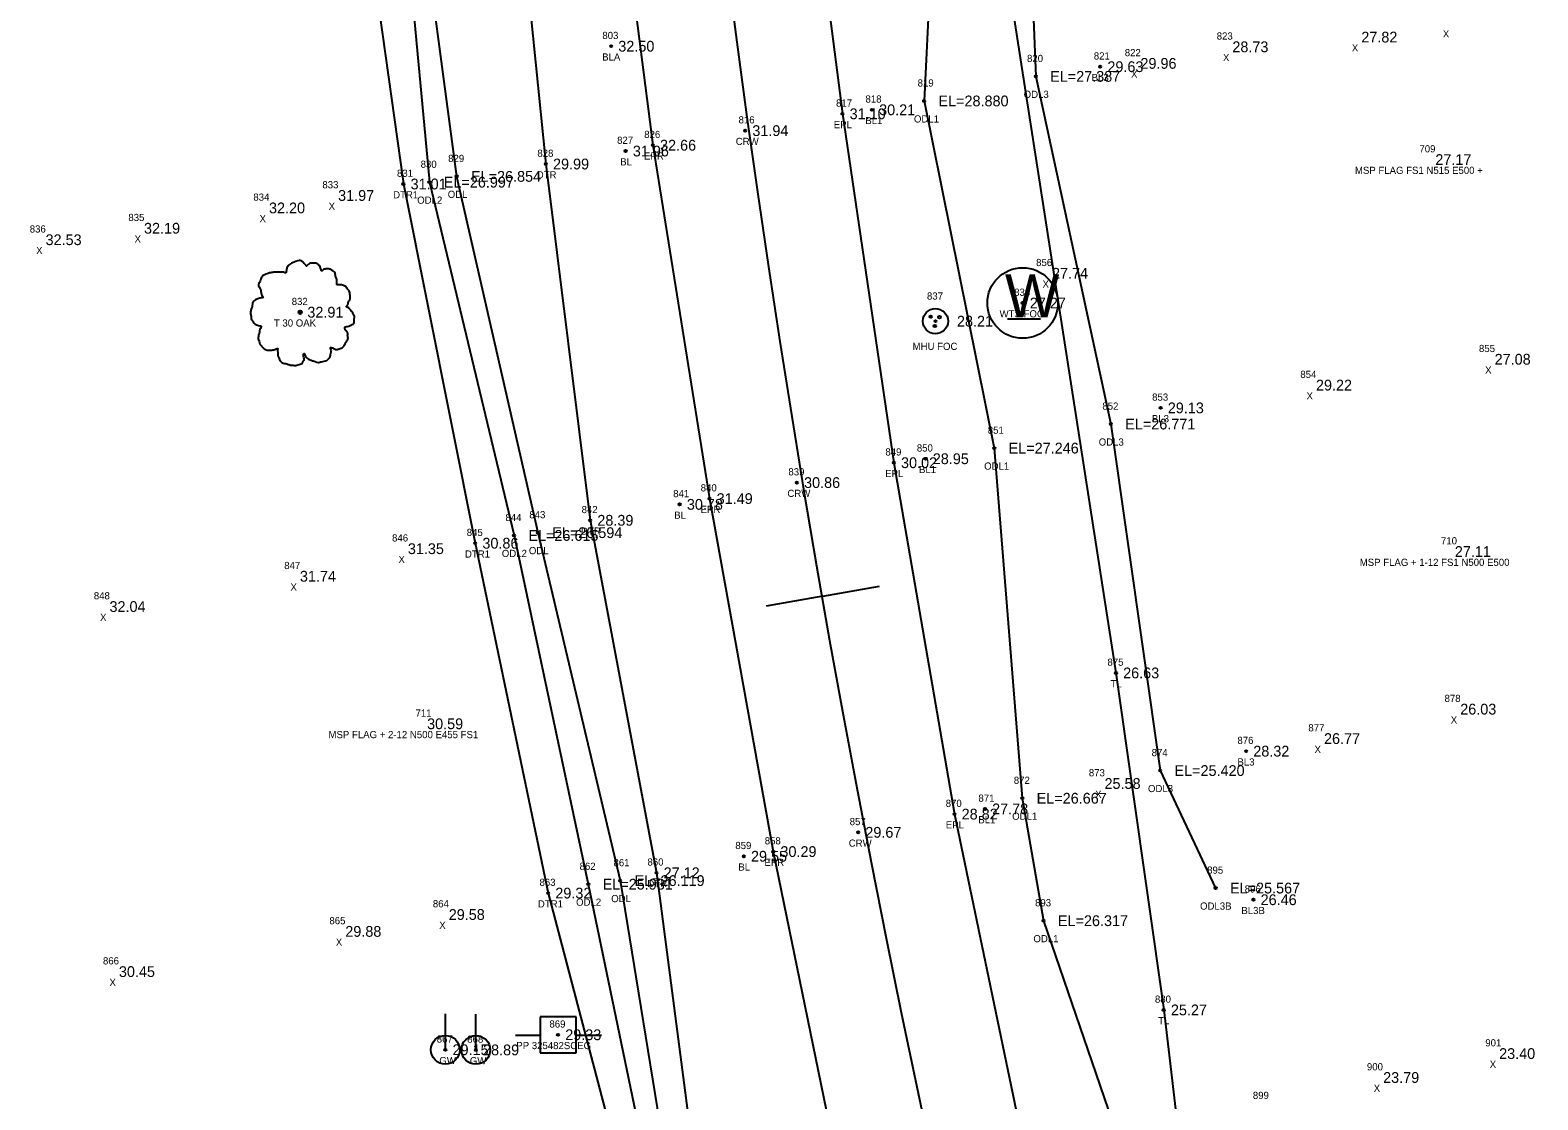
# Model space of a CAD drawing. Extents: x 2042117 to 2045853, y 303080 to 309569.
# Drawn here: x 2042758.3 to 2042968.2, y 306948.4 to 307097.3 of the extents above; entities that cross this region are included whole.
import ezdxf

# ---------------------------------------------------------------- set-up
doc = ezdxf.new("R2010")
doc.units = 0
for name, color, linetype in [('RD_DTM_BkLn_txCode', 7, 'Continuous'), ('RD_EX_DR_Inlet', 7, 'Continuous'), ('RD_EX_H2O', 7, 'Continuous'), ('RD_EX_H2O_txCode', 7, 'Continuous'), ('RD_EX_Misc_txCode', 7, 'Continuous'), ('RD_EX_Road', 7, 'Continuous'), ('RD_EX_Road_txCode', 7, 'Continuous'), ('RD_EX_TX_H2O_ELEV', 7, 'Continuous'), ('RD_EX_TX_Misc_ELEV', 7, 'Continuous'), ('RD_EX_TX_Road_ELEV', 7, 'Continuous'), ('RD_EX_TX_UT_ELEV', 7, 'Continuous'), ('RD_EX_TX_VEG_ELEV', 7, 'Continuous'), ('RD_EX_UT', 7, 'Continuous'), ('RD_EX_UT_txCode', 7, 'Continuous'), ('RD_EX_VEG', 7, 'Continuous'), ('RD_EX_VEG_txCode', 7, 'Continuous'), ('RD_HC_Cl', 7, 'Continuous'), ('RD_HC_Data_Tic', 7, 'Continuous'), ('RD_HC_Survey_ELEV', 7, 'Continuous'), ('RD_HC_Survey_txCode', 7, 'Continuous'), ('RD_SMD_Locator', 7, 'Continuous')]:
    doc.layers.add(name, color=color, linetype=linetype)

msp = doc.modelspace()

# ---------------------------------------------------------------- linework, layer by layer
at = {"layer": 'RD_EX_DR_Inlet'}
for centre, radius in [((2042884.32, 307056.83), 1.75), ((2042883.66, 307057.46), 0.175), ((2042884.88, 307057.39), 0.175), ((2042884.24, 307056.17), 0.175)]:
    msp.add_circle(centre, radius, dxfattribs=at)
at = {"layer": 'RD_EX_H2O'}
for points in [[(2042865.43, 307427.05), (2042866.84, 307378.87), (2042866.82, 307329.93), (2042876.23, 307282.16), (2042878.43, 307232.86), (2042875.08, 307184.77), (2042887.19, 307136.65), (2042884.32, 307120.02), (2042882.74, 307087.49), (2042892.51, 307039.16), (2042896.41, 306990.42), (2042899.37, 306973.37), (2042910.05, 306942.23), (2042920.75, 306896.67), (2042927.15, 306846.78), (2042945.6, 306801.59), (2042960.32, 306754.61), (2042976.65, 306708.74), (2042994.63, 306662.76), (2043013.3, 306616.98), (2043029.17, 306571.91), (2043050.77, 306528.53)], [(2042809.74, 307126.16), (2042806.56, 307122.63), (2042790.31, 307116.78), (2042788.49, 307114.78), (2042791.89, 307113.57), (2042804.81, 307114.94), (2042810.25, 307075.93), (2042820.25, 307025.92), (2042830.4, 306977.21), (2042843.29, 306928.12), (2042852.91, 306878.24), (2042864.55, 306828.43), (2042879.23, 306781.72), (2042889.45, 306748.73), (2042886.16, 306741.98), (2042888.34, 306727.94), (2042896.13, 306676.35), (2042885.67, 306665.43), (2042857.25, 306612.72)], [(2042809.74, 307126.16), (2042815.01, 307124.31), (2042821.79, 307118.99), (2042825.8, 307110.2), (2042827.88, 307100.21), (2042830.08, 307078.71), (2042836.25, 307029.11), (2042845.48, 306980.04), (2042852.07, 306929.46), (2042864.58, 306881.26), (2042879.31, 306833.06), (2042893.37, 306784.78), (2042908.76, 306736.23), (2042928.77, 306689.39), (2042938.94, 306669.11)], [(2042896.98, 307122.86), (2042898.29, 307090.91), (2042908.74, 307042.51), (2042915.6, 306994.27), (2042923.33, 306977.91)], [(2042810.02, 307117.36), (2042813.87, 307076.18), (2042825.65, 307027), (2042835.99, 306978.45), (2042846.19, 306929.27), (2042857.5, 306879.97), (2042870.3, 306830.67), (2042885.37, 306782.68), (2042895.57, 306748.28), (2042892.03, 306740.63), (2042891.66, 306731.27), (2042905.95, 306680.58), (2042906.87, 306643.18), (2042864.97, 306605.63)], [(2042812.2, 307117.75), (2042817.66, 307076.99), (2042828.97, 307027.39), (2042840.42, 306978.95), (2042848.44, 306929.66), (2042859.84, 306880.36), (2042873.68, 306831.67), (2042888.54, 306783.43), (2042900.59, 306749.27), (2042902.9, 306733.67), (2042926.04, 306688.21), (2042936.45, 306668.37), (2042947.44, 306643.99), (2042966.18, 306597.91), (2042985.34, 306551.14), (2042987.61, 306538.59)]]:
    msp.add_lwpolyline(points, dxfattribs=at)
at = {"layer": 'RD_EX_Road'}
for points in [[(2042828.36, 307428.87), (2042826.99, 307378.91), (2042826.88, 307329.29), (2042828.01, 307279.82), (2042830.5, 307230.24), (2042834.09, 307180.37), (2042835.89, 307157.73), (2042833.55, 307154.38), (2042836.54, 307132.83), (2042837.33, 307130.11), (2042837.64, 307128.77), (2042839.22, 307126.16), (2042844.98, 307081.33), (2042852.86, 307032.13), (2042861.74, 306982.99), (2042871.66, 306934.62), (2042883.38, 306885.88), (2042895.94, 306837.56), (2042909.76, 306789.89)], [(2042855.03, 307427.78), (2042853.64, 307379.19), (2042853.31, 307329.44), (2042854.43, 307281.38), (2042857.15, 307232.07), (2042860.27, 307183.35), (2042865.16, 307133.89), (2042871.37, 307085.7), (2042878.53, 307037.13), (2042886.97, 306988.21), (2042897.02, 306940.01), (2042908.28, 306892.66), (2042921.09, 306844.85), (2042934.41, 306798.2)]]:
    msp.add_lwpolyline(points, dxfattribs=at)
at = {"layer": 'RD_EX_UT'}
for p, q in [((2042894.34, 307057.15), (2042898.96, 307057.15)), ((2042816.09, 306955.4), (2042816.09, 306960.4)), ((2042820.34, 306955.38), (2042820.34, 306960.38)), ((2042834.28, 306959.99), (2042829.28, 306959.99)), ((2042829.28, 306959.99), (2042829.28, 306954.99)), ((2042834.28, 306954.99), (2042834.28, 306959.99)), ((2042825.84, 306957.43), (2042829.31, 306957.43)), ((2042834.2, 306957.43), (2042837.84, 306957.43)), ((2042829.28, 306954.99), (2042834.28, 306954.99))]:
    msp.add_line(p, q, dxfattribs=at)
for centre, radius in [((2042896.46, 307059.36), 4.91), ((2042816.09, 306955.4), 2), ((2042820.34, 306955.38), 2)]:
    msp.add_circle(centre, radius, dxfattribs=at)
at = {"layer": 'RD_EX_VEG'}
msp.add_lwpolyline([(2042885.61, 307482.85), (2042881.1, 307379.92), (2042880.44, 307351.7), (2042880.19, 307284.9), (2042884.99, 307224.08), (2042886.48, 307195.22), (2042890.83, 307127.55), (2042909.45, 307007.86), (2042916.1, 306960.95), (2042918.56, 306940.03), (2042926.66, 306909), (2042942.91, 306849.91), (2042954.33, 306802.72), (2042963.56, 306806.84), (2042974.33, 306847.25), (2043002.07, 306860.54), (2043032.14, 306846.51)], dxfattribs=at)
for centre, radius in [((2042795.88, 307058.08), 0.25), ((2042795.87, 307058.06), 0.0001)]:
    msp.add_circle(centre, radius, dxfattribs=at)
for points in [[(2042796.02, 307065.25), (2042795.72, 307065.27), (2042795.39, 307065.17), (2042795.14, 307065.07), (2042794.92, 307065), (2042794.69, 307064.9), (2042794.39, 307064.72), (2042794.17, 307064.52), (2042794.04, 307064.27), (2042793.99, 307064.05), (2042793.94, 307063.77), (2042793.94, 307063.6), (2042793.82, 307063.57), (2042793.67, 307063.6), (2042793.42, 307063.67), (2042793.17, 307063.67), (2042792.92, 307063.67), (2042792.57, 307063.65), (2042792.22, 307063.65), (2042791.94, 307063.6), (2042791.62, 307063.55), (2042791.24, 307063.42), (2042790.89, 307063.3), (2042790.59, 307063.05), (2042790.34, 307062.57), (2042790.22, 307062.22), (2042790.07, 307061.97), (2042790.22, 307061.52), (2042790.39, 307061.17), (2042790.42, 307060.97), (2042790.49, 307060.55), (2042790.59, 307060.33), (2042790.72, 307060.13), (2042790.64, 307060.1), (2042790.27, 307060.05), (2042789.97, 307059.95), (2042789.54, 307059.73), (2042789.32, 307059.5), (2042789.22, 307059.18), (2042789.19, 307058.83), (2042789.09, 307058.63), (2042789.02, 307058.35), (2042788.99, 307058.28), (2042788.94, 307057.95), (2042789.04, 307057.5), (2042789.07, 307057.15), (2042789.19, 307056.93), (2042789.34, 307056.75), (2042789.52, 307056.5), (2042789.92, 307056.28), (2042790.24, 307056.18), (2042790.44, 307056.15), (2042790.27, 307055.65), (2042790.22, 307055.3), (2042790.09, 307054.9), (2042790.09, 307054.83), (2042790.04, 307054.35), (2042790.19, 307054.03), (2042790.27, 307053.65), (2042790.44, 307053.43), (2042790.72, 307053.13), (2042791.04, 307052.9), (2042791.54, 307052.78), (2042791.94, 307052.8), (2042792.52, 307052.98), (2042792.77, 307053.05), (2042792.74, 307052.88), (2042792.77, 307052.5), (2042792.77, 307052.08), (2042792.92, 307051.75), (2042793.02, 307051.48), (2042793.17, 307051.23), (2042793.49, 307051), (2042793.89, 307050.93), (2042794.32, 307050.78), (2042794.77, 307050.7), (2042795.27, 307050.68), (2042795.87, 307050.83), (2042796.14, 307050.95), (2042796.24, 307051.13), (2042796.44, 307051.5), (2042796.39, 307051.73), (2042796.42, 307052.33), (2042796.52, 307052.15), (2042796.69, 307051.8), (2042797.19, 307051.5), (2042797.59, 307051.33), (2042798.07, 307051.18), (2042798.36, 307051.1), (2042798.84, 307051.18), (2042799.21, 307051.25), (2042799.59, 307051.38), (2042799.89, 307051.65), (2042800.06, 307051.93), (2042800.11, 307052.2), (2042800.19, 307052.58), (2042800.24, 307052.75)], [(2042800.24, 307052.75), (2042800.16, 307052.93), (2042800.11, 307053.18), (2042800.19, 307053.15), (2042800.36, 307053.1), (2042800.64, 307052.98), (2042800.86, 307052.9), (2042801.19, 307052.93), (2042801.46, 307053.03), (2042801.91, 307053.3), (2042802.19, 307053.78), (2042802.46, 307054.18), (2042802.54, 307054.5), (2042802.49, 307054.73), (2042802.46, 307055.23), (2042802.26, 307055.48), (2042802.21, 307055.6), (2042802.11, 307056), (2042802.19, 307056.05), (2042802.46, 307056.1), (2042802.84, 307056.23), (2042803.11, 307056.35), (2042803.34, 307056.53), (2042803.41, 307056.75), (2042803.39, 307057.15), (2042803.44, 307057.55), (2042803.36, 307057.7), (2042803.26, 307057.85), (2042803.19, 307058.05), (2042803.04, 307058.2), (2042802.94, 307058.35), (2042802.84, 307058.45), (2042802.71, 307058.6), (2042802.54, 307058.73), (2042802.39, 307058.78), (2042802.34, 307058.93), (2042802.49, 307059.13), (2042802.54, 307059.23), (2042802.56, 307059.45), (2042802.79, 307059.8), (2042802.84, 307060.2), (2042802.79, 307060.62), (2042802.74, 307060.9), (2042802.59, 307061.17), (2042802.39, 307061.42), (2042802.26, 307061.6), (2042802.09, 307061.72), (2042801.76, 307061.85), (2042801.51, 307061.9), (2042801.16, 307061.9), (2042800.96, 307061.95), (2042800.99, 307062), (2042800.99, 307062.15), (2042800.99, 307062.42), (2042800.91, 307062.87), (2042800.76, 307063.37), (2042800.76, 307063.4), (2042800.66, 307063.65), (2042800.44, 307063.85), (2042800.26, 307063.95), (2042800.06, 307064.07), (2042799.81, 307064.1), (2042799.51, 307064.1), (2042799.24, 307064.05), (2042799.04, 307063.95), (2042798.86, 307063.82), (2042798.79, 307063.97), (2042798.69, 307064.27), (2042798.64, 307064.42), (2042798.49, 307064.6), (2042798.27, 307064.8), (2042797.82, 307064.92), (2042797.19, 307064.85), (2042796.89, 307064.65), (2042796.74, 307064.47), (2042796.69, 307064.6), (2042796.49, 307064.8), (2042796.39, 307064.97), (2042796.22, 307065.1), (2042796.07, 307065.2), (2042795.97, 307065.25)]]:
    msp.add_spline(points, degree=3, dxfattribs=at)
at = {"layer": 'RD_HC_Cl'}
msp.add_arc((2044751.25, 307348.43), 1911.29, 137.68184, 219.86836, dxfattribs=at)
at = {"layer": 'RD_HC_Data_Tic'}
for q in [(2042876.52, 307019.93), (2042860.76, 307017.17)]:
    msp.add_line((2042868.64, 307018.55), q, dxfattribs=at)
at = {"layer": 'RD_SMD_Locator'}
for centre in [(2042839.17, 307095.11), (2042907.26, 307092.26), (2042898.29, 307090.91), (2042875.48, 307086.26), (2042882.74, 307087.49), (2042871.37, 307085.7), (2042857.83, 307083.36), (2042841.19, 307080.52), (2042844.98, 307081.33), (2042830.08, 307078.71), (2042810.25, 307075.93), (2042813.87, 307076.18), (2042817.66, 307076.99), (2042896.46, 307059.36), (2042795.88, 307058.08), (2042884.32, 307056.83), (2042915.67, 307044.76), (2042908.74, 307042.51), (2042882.95, 307037.68), (2042892.51, 307039.16), (2042878.53, 307037.13), (2042865.03, 307034.36), (2042848.71, 307031.33), (2042852.86, 307032.13), (2042836.25, 307029.11), (2042825.65, 307027), (2042828.97, 307027.39), (2042820.25, 307025.92), (2042909.45, 307007.86), (2042927.57, 306996.97), (2042915.6, 306994.27), (2042896.41, 306990.42), (2042886.97, 306988.21), (2042891.21, 306988.93), (2042873.56, 306985.67), (2042861.74, 306982.99), (2042857.64, 306982.34), (2042840.42, 306978.95), (2042845.48, 306980.04), (2042830.4, 306977.21), (2042835.99, 306978.45), (2042923.33, 306977.91), (2042928.59, 306976.29), (2042899.37, 306973.37), (2042916.1, 306960.95), (2042831.78, 306957.49), (2042816.09, 306955.4), (2042820.34, 306955.38)]:
    msp.add_circle(centre, 0.15, dxfattribs=at)

# ---------------------------------------------------------------- texts
at = {"layer": 'RD_DTM_BkLn_txCode'}
for s, p in [('803', (2042837.95, 307096.11)), ('821', (2042906.37, 307093.26)), ('BLA', (2042837.92, 307093.11)), ('BL3', (2042906.06, 307090.26)), ('818', (2042874.58, 307087.26)), ('BL1', (2042874.56, 307084.26)), ('827', (2042840, 307081.52)), ('BL', (2042840.43, 307078.52)), ('853', (2042914.49, 307045.76)), ('BL3', (2042914.46, 307042.76)), ('850', (2042881.73, 307038.68)), ('BL1', (2042882.03, 307035.68)), ('841', (2042847.81, 307032.33)), ('BL', (2042847.95, 307029.33)), ('876', (2042926.36, 306997.97)), ('BL3', (2042926.36, 306994.97)), ('871', (2042890.31, 306989.93)), ('BL1', (2042890.29, 306986.93)), ('859', (2042856.46, 306983.34)), ('BL', (2042856.88, 306980.34)), ('896', (2042927.38, 306977.29)), ('BL3B', (2042926.91, 306974.29))]:
    msp.add_text(s, height=1, dxfattribs=at).set_placement(p)
at = {"layer": 'RD_EX_H2O_txCode'}
for s, p in [('820', (2042897.07, 307092.91)), ('819', (2042881.84, 307089.49)), ('ODL3', (2042896.6, 307087.91)), ('ODL1', (2042881.33, 307084.49)), ('829', (2042816.48, 307078.99)), ('828', (2042828.9, 307079.71)), ('831', (2042809.36, 307076.93)), ('830', (2042812.65, 307078.18)), ('DTR', (2042828.81, 307076.71)), ('DTR1', (2042808.82, 307073.93)), ('ODL2', (2042812.17, 307073.18)), ('ODL', (2042816.42, 307073.99)), ('852', (2042907.56, 307044.51)), ('851', (2042891.61, 307041.16)), ('ODL3', (2042907.05, 307039.51)), ('ODL1', (2042891.1, 307036.16)), ('844', (2042824.46, 307029)), ('843', (2042827.78, 307029.39)), ('842', (2042835.06, 307030.11)), ('845', (2042819.07, 307026.92)), ('DTR', (2042834.98, 307027.11)), ('ODL2', (2042823.95, 307024)), ('ODL', (2042827.72, 307024.39)), ('DTR1', (2042818.82, 307023.92)), ('874', (2042914.42, 306996.27)), ('872', (2042895.23, 306992.42)), ('ODL3', (2042913.91, 306991.27)), ('ODL1', (2042895, 306987.42)), ('862', (2042834.78, 306980.45)), ('861', (2042839.5, 306980.95)), ('860', (2042844.23, 306981.04)), ('895', (2042922.15, 306979.91)), ('863', (2042829.2, 306978.21)), ('DTR', (2042844.21, 306978.04)), ('ODL', (2042839.18, 306975.95)), ('DTR1', (2042828.97, 306975.21)), ('ODL2', (2042834.29, 306975.45)), ('893', (2042898.19, 306975.37)), ('ODL3B', (2042921.16, 306974.91)), ('ODL1', (2042897.96, 306970.37))]:
    msp.add_text(s, height=1, dxfattribs=at).set_placement(p)
at = {"layer": 'RD_EX_Misc_txCode'}
for s, p in [('823', (2042923.48, 307096.03)), ('X', (2042954.96, 307096.33)), ('822', (2042910.68, 307093.72)), ('X', (2042942.29, 307094.38)), ('X', (2042924.35, 307093.03)), ('X', (2042911.55, 307090.72)), ('709', (2042951.7, 307080.33)), ('MSP FLAG FS1 N515 E500 +', (2042942.72, 307077.33)), ('833', (2042798.97, 307075.33)), ('834', (2042789.36, 307073.6)), ('X', (2042799.84, 307072.33)), ('835', (2042771.96, 307070.77)), ('X', (2042790.22, 307070.6)), ('836', (2042758.23, 307069.17)), ('X', (2042759.12, 307066.17)), ('X', (2042772.82, 307067.77)), ('856', (2042898.34, 307064.5)), ('X', (2042899.23, 307061.5)), ('855', (2042959.99, 307052.53)), ('X', (2042960.85, 307049.53)), ('854', (2042935.12, 307048.93)), ('X', (2042935.98, 307045.93)), ('846', (2042808.67, 307026.16)), ('710', (2042954.7, 307025.76)), ('847', (2042793.66, 307022.32)), ('X', (2042809.56, 307023.16)), ('MSP FLAG + 1-12 FS1 N500 E500', (2042943.39, 307022.76)), ('848', (2042767.15, 307018.1)), ('X', (2042794.53, 307019.32)), ('X', (2042768.02, 307015.1)), ('878', (2042955.2, 307003.82)), ('711', (2042811.94, 307001.78)), ('877', (2042936.24, 306999.72)), ('X', (2042956.06, 307000.82)), ('MSP FLAG + 2-12 N500 E455 FS1', (2042799.82, 306998.78)), ('X', (2042937.1, 306996.72)), ('873', (2042905.68, 306993.47)), ('X', (2042906.55, 306990.47)), ('864', (2042814.35, 306975.23)), ('865', (2042799.95, 306972.88)), ('X', (2042815.24, 306972.23)), ('X', (2042800.84, 306969.88)), ('866', (2042768.42, 306967.28)), ('X', (2042769.33, 306964.28)), ('901', (2042960.87, 306955.87)), ('X', (2042961.49, 306952.87)), ('900', (2042944.39, 306952.54)), ('899', (2042928.51, 306948.55)), ('X', (2042945.34, 306949.54))]:
    msp.add_text(s, height=1, dxfattribs=at).set_placement(p)
at = {"layer": 'RD_EX_Road_txCode'}
for s, p in [('817', (2042870.48, 307086.7)), ('EPL', (2042870.17, 307083.7)), ('826', (2042843.78, 307082.33)), ('EPR', (2042843.75, 307079.33)), ('849', (2042877.35, 307038.13)), ('EPL', (2042877.32, 307035.13)), ('840', (2042851.64, 307033.13)), ('EPR', (2042851.63, 307030.13)), ('870', (2042885.75, 306989.21)), ('EPL', (2042885.76, 306986.21)), ('858', (2042860.56, 306983.99)), ('EPR', (2042860.51, 306980.99))]:
    msp.add_text(s, height=1, dxfattribs=at).set_placement(p)
at = {"layer": 'RD_EX_TX_H2O_ELEV'}
for s, p in [('EL=27.387', (2042900.29, 307090.16)), ('EL=28.880', (2042884.74, 307086.74)), ('EL=26.854', (2042819.66, 307076.24)), ('29.99', (2042831.08, 307077.96)), ('31.01', (2042811.25, 307075.18)), ('EL=26.997', (2042815.87, 307075.43)), ('EL=26.771', (2042910.74, 307041.76)), ('EL=27.246', (2042894.51, 307038.41)), ('28.39', (2042837.25, 307028.36)), ('EL=26.615', (2042827.65, 307026.25)), ('EL=26.594', (2042830.97, 307026.64)), ('30.86', (2042821.25, 307025.17)), ('EL=25.420', (2042917.6, 306993.52)), ('EL=26.667', (2042898.41, 306989.67)), ('EL=25.931', (2042837.99, 306977.7)), ('EL=26.119', (2042842.42, 306978.2)), ('27.12', (2042846.48, 306979.29)), ('29.32', (2042831.4, 306976.46)), ('EL=25.567', (2042925.33, 306977.16)), ('EL=26.317', (2042901.37, 306972.62))]:
    msp.add_text(s, height=1.5, dxfattribs=at).set_placement(p)
at = {"layer": 'RD_EX_TX_Misc_ELEV'}
for s, p in [('27.82', (2042943.61, 307095.63)), ('32.50', (2042840.17, 307094.36)), ('28.73', (2042925.66, 307094.28)), ('29.63', (2042908.26, 307091.51)), ('29.96', (2042912.86, 307091.97)), ('30.21', (2042876.48, 307085.51)), ('31.96', (2042842.19, 307079.77)), ('27.17', (2042953.92, 307078.58)), ('32.20', (2042791.54, 307071.85)), ('31.97', (2042801.16, 307073.58)), ('32.19', (2042774.14, 307069.02)), ('32.53', (2042760.43, 307067.42)), ('27.74', (2042900.55, 307062.75)), ('27.08', (2042962.17, 307050.78)), ('29.22', (2042937.3, 307047.18)), ('29.13', (2042916.67, 307044.01)), ('28.95', (2042883.95, 307036.93)), ('30.78', (2042849.71, 307030.58)), ('31.35', (2042810.87, 307024.41)), ('27.11', (2042956.63, 307024.01)), ('31.74', (2042795.84, 307020.57)), ('32.04', (2042769.33, 307016.35)), ('26.03', (2042957.38, 307002.07)), ('30.59', (2042813.55, 307000.03)), ('28.32', (2042928.57, 306996.22)), ('26.77', (2042938.42, 306997.97)), ('25.58', (2042907.86, 306991.72)), ('27.78', (2042892.21, 306988.18)), ('29.55', (2042858.64, 306981.59)), ('26.46', (2042929.59, 306975.54)), ('29.58', (2042816.56, 306973.48)), ('29.88', (2042802.16, 306971.13)), ('30.45', (2042770.64, 306965.53)), ('23.40', (2042962.8, 306954.12)), ('23.79', (2042946.65, 306950.79))]:
    msp.add_text(s, height=1.5, dxfattribs=at).set_placement(p)
at = {"layer": 'RD_EX_TX_Road_ELEV'}
for s, p in [('31.10', (2042872.37, 307084.95)), ('32.66', (2042845.98, 307080.58)), ('30.02', (2042879.53, 307036.38)), ('31.49', (2042853.86, 307031.38)), ('28.82', (2042887.97, 306987.46)), ('30.29', (2042862.74, 306982.24))]:
    msp.add_text(s, height=1.5, dxfattribs=at).set_placement(p)
at = {"layer": 'RD_EX_TX_UT_ELEV'}
for s, p in [('27.27', (2042897.46, 307058.61)), ('28.21', (2042887.32, 307056.08)), ('29.15', (2042817.09, 306954.65)), ('28.89', (2042821.34, 306954.63))]:
    msp.add_text(s, height=1.5, dxfattribs=at).set_placement(p)
at = {"layer": 'RD_EX_TX_VEG_ELEV'}
for s, p in [('32.91', (2042796.88, 307057.33)), ('26.63', (2042910.45, 307007.11)), ('25.27', (2042917.1, 306960.2))]:
    msp.add_text(s, height=1.5, dxfattribs=at).set_placement(p)
at = {"layer": 'RD_EX_UT'}
msp.add_text('W', height=6, dxfattribs=at).set_placement((2042894, 307057.36))
at = {"layer": 'RD_EX_UT_txCode'}
for s, p in [('837', (2042883.14, 307059.83)), ('838', (2042895.28, 307060.36)), ('WTS FOC', (2042893.25, 307057.36)), ('MHU FOC', (2042881.14, 307052.83)), ('869', (2042830.58, 306958.49)), ('867', (2042814.89, 306956.4)), ('868', (2042819.14, 306956.38)), ('PP 325482SCEG', (2042825.97, 306955.49)), ('GW', (2042815.25, 306953.4)), ('GW', (2042819.5, 306953.38))]:
    msp.add_text(s, height=1, dxfattribs=at).set_placement(p)
at = {"layer": 'RD_EX_VEG_txCode'}
for s, p in [('832', (2042794.7, 307059.08)), ('T 30 OAK', (2042792.22, 307056.08)), ('875', (2042908.27, 307008.86)), ('TL', (2042908.68, 307005.86)), ('880', (2042914.88, 306961.95)), ('TL', (2042915.33, 306958.95))]:
    msp.add_text(s, height=1, dxfattribs=at).set_placement(p)
at = {"layer": 'RD_HC_Survey_ELEV'}
for s, p in [('31.94', (2042858.83, 307082.61)), ('30.86', (2042866.03, 307033.61)), ('29.67', (2042874.56, 306984.92)), ('29.33', (2042832.78, 306956.74))]:
    msp.add_text(s, height=1.5, dxfattribs=at).set_placement(p)
at = {"layer": 'RD_HC_Survey_txCode'}
for s, p in [('816', (2042856.91, 307084.36)), ('CRW', (2042856.52, 307081.36)), ('839', (2042863.85, 307035.36)), ('CRW', (2042863.71, 307032.36)), ('857', (2042872.38, 306986.67)), ('CRW', (2042872.25, 306983.67))]:
    msp.add_text(s, height=1, dxfattribs=at).set_placement(p)

doc.saveas('drawing.dxf')
